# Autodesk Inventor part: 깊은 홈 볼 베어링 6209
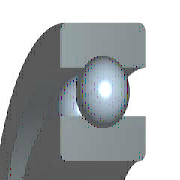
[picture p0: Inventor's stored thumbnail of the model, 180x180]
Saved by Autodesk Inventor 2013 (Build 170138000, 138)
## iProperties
IsCustomPart: 1
Created: 2012-02
Part Number: 깊은 홈 볼 베어링 6209
Material: 강철, 연강
Description: 깊은 그루부 볼 베어링
Document SubType Name: Modeling
Standard: JIS B 1521
Designer: mdu-01
Standards Organization: JIS
Language: ko-KR
Size Designation: 6209 45x85x19
Categories: <MemberInstance><Categories><Category DisplayName="샤프트 부품" InternalName="7f7aeb1f-a693-4053-b835-cee3144e0d98" Mnemonic="SHFT"><Category DisplayName="베어링" Inter
Density: 1 g/cm^3
Author: mdu-01
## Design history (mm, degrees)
sketch "스케치" dims "d0" = 10.4 (= -0.26 x WD + 0.26 x BD)
  geometry: L1 (4.3, 32.5)-(14.7, 32.5); L2 (9.5, 32.5)-(9.5, 27.3); L3 (9.5, 32.5)-(9.5, 37.7); L4 (5.636, 29.02)-(0, 29.02); L5 (0, 22.5)-(19, 22.5); L6 (5.636, 35.98)-(0, 35.98); L7 (0, 42.5)-(19, 42.5); L8 (19, 22.5)-(19, 29.02); L9 (13.364, 29.02)-(19, 29.02); L10 (13.364, 35.98)-(19, 35.98); L11 (19, 42.5)-(19, 35.98); L12 (-1.4, 0)-(8.4, 0) reference; L13 (0, -0.3)-(0, 5.3) reference
  constraints: 22 end point, 4 point on line, 2 collinear, 2 perpendicular, 2 symmetric about line, 1 midpoint, 1 parallel, 14 other
  dimensions: "d9" = 45 diameter of L5 L12 (= WD); "d11" = 85 diameter of L7 L12 (= BD); "d12" = 19 distance between parallel lines of L8 L13 (= KB); "d13" = 58.04 diameter of L9 L12 (= 0.326 x BD + 0.674 x WD)
revolve "본체" stored, may be unused: angle "d6" = 90 deg
revolve "볼" stored, may be unused: angle "d7" = 90 deg
pattern_circular "IDS_ARRAYBALL[SIMPL:T]" dims angle "d3" = 360 deg
body "Solid1"
fillet "모깎기1" dims "d1" = 1.1 (= KRS)
other parameters: "WD" = 45 [user parameter; used in 5 equation terms], "BD" = 85 [user parameter; used in 5 equation terms], "KB" = 19 [user parameter; used in 1 equation term], "KRS" = 1.1 [user parameter; used in 1 equation term], "d4" = 0, "d5" = 0, "d8" = 0, "d14" = 0, "d15" = 0, "BBA" = 0 [user parameter], "BC0" = 2.16e+07 [user parameter], "BC" = 3.32e+07 [user parameter], "BR" = 42.5 (= 0.5 x BD) [user parameter], "WR" = 22.5 (= 0.5 x WD) [user parameter]
